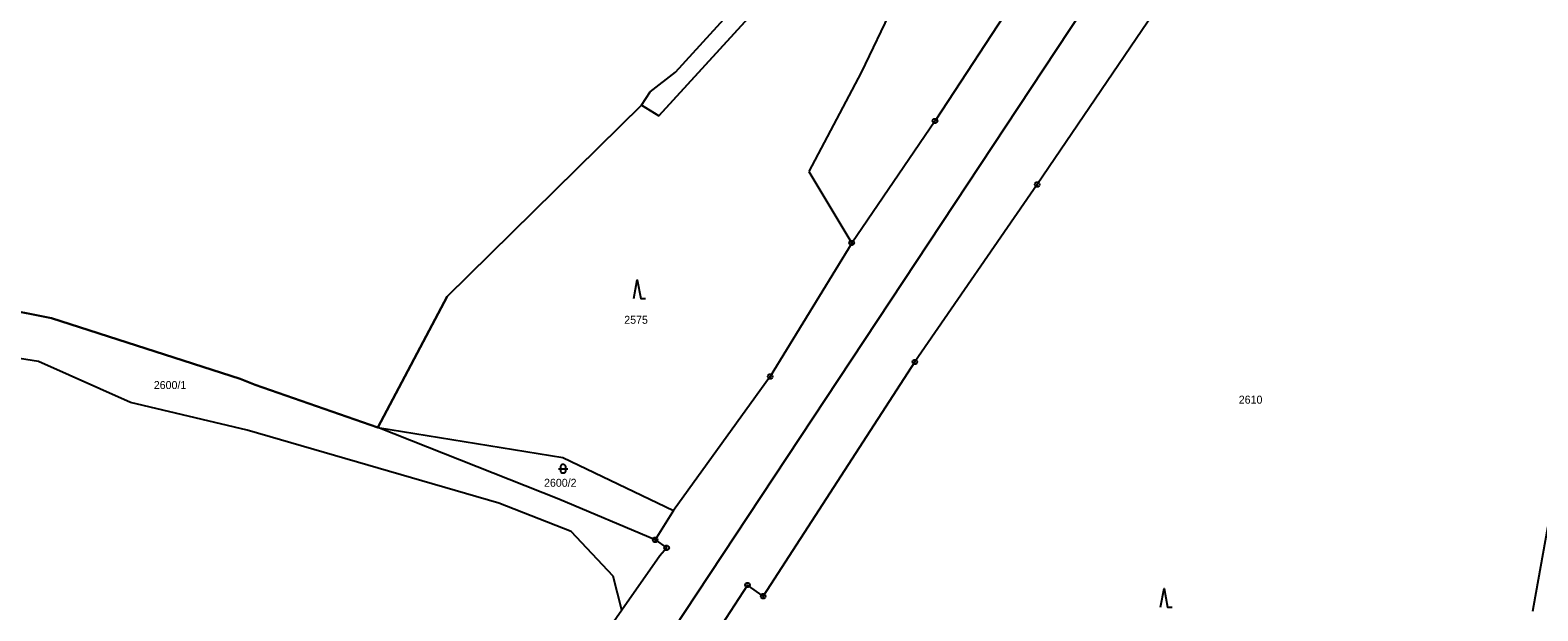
# Model space of a CAD drawing. Extents: x -760611 to -758411, y -1176479 to -1174807.
# Drawn here: x -759798.8 to -759476.2, y -1176113.5 to -1175989.4 of the extents above; entities that cross this region are included whole.
import ezdxf

# ---------------------------------------------------------------- set-up
doc = ezdxf.new("R2010")
doc.units = 0
for name, color, linetype in [('1', 7, 'Continuous'), ('11', 7, 'Continuous'), ('2', 7, 'Continuous'), ('3', 7, 'Continuous'), ('6', 7, 'Continuous'), ('8', 7, 'Continuous')]:
    doc.layers.add(name, color=color, linetype=linetype)

msp = doc.modelspace()

# ---------------------------------------------------------------- linework, layer by layer
at = {"layer": '1'}
for p, q in [((-759578.18, -1175967.56), (-759605.19, -1176008.78)), ((-759660.74, -1175998.38), (-759641.25, -1175976.94)), ((-759555.51, -1175981.46), (-759583.34, -1176022.38)), ((-759614.19, -1175984.28), (-759620.96, -1175998.45)), ((-759645.08, -1175986.7), (-759664.29, -1176007.68)), ((-759666.09, -1176002.55), (-759660.74, -1175998.38)), ((-759620.96, -1175998.45), (-759632.18, -1176019.57)), ((-759667.97, -1176005.44), (-759709.52, -1176046.31)), ((-759667.97, -1176005.44), (-759666.09, -1176002.55)), ((-759664.29, -1176007.68), (-759667.97, -1176005.44)), ((-759605.19, -1176008.78), (-759623.01, -1176034.88)), ((-759632.18, -1176019.57), (-759623.01, -1176034.88)), ((-759583.34, -1176022.38), (-759609.49, -1176060.32)), ((-759623.01, -1176034.88), (-759640.44, -1176063.43)), ((-759794.18, -1176050.97), (-759814.38, -1176046.99)), ((-759709.52, -1176046.31), (-759724.36, -1176074.33)), ((-759753.8, -1176063.91), (-759794.18, -1176050.97)), ((-759796.99, -1176060.22), (-759818.71, -1176056.82)), ((-759777.26, -1176068.95), (-759796.99, -1176060.22)), ((-759609.49, -1176060.32), (-759641.95, -1176110.4)), ((-759640.44, -1176063.43), (-759661.14, -1176092.07)), ((-759750.6, -1176065.19), (-759753.8, -1176063.91)), ((-759724.36, -1176074.33), (-759750.6, -1176065.19)), ((-759752.37, -1176074.92), (-759777.26, -1176068.95)), ((-759469.14, -1176067.99), (-759477.14, -1176112.43)), ((-759698.51, -1176090.48), (-759752.37, -1176074.92)), ((-759685.68, -1176089.67), (-759724.36, -1176074.33)), ((-759724.36, -1176074.33), (-759684.84, -1176080.74)), ((-759684.84, -1176080.74), (-759661.14, -1176092.07)), ((-759683.03, -1176096.6), (-759698.51, -1176090.48)), ((-759665.06, -1176098.36), (-759685.68, -1176089.67)), ((-759661.14, -1176092.07), (-759665.06, -1176098.36)), ((-759674.01, -1176106.12), (-759683.03, -1176096.6)), ((-759665.06, -1176098.36), (-759662.59, -1176100.07)), ((-759664.06, -1176101.76), (-759672.16, -1176113.37)), ((-759662.59, -1176100.07), (-759664.06, -1176101.76)), ((-759672.16, -1176113.37), (-759674.01, -1176106.12)), ((-759645.3, -1176108.02), (-759655.18, -1176123.17)), ((-759641.95, -1176110.4), (-759645.3, -1176108.02)), ((-759672.16, -1176113.37), (-759732.47, -1176199.81)), ((-759477.14, -1176112.43), (-759477.37, -1176113.69))]:
    msp.add_line(p, q, dxfattribs=at)
at = {"layer": '11'}
msp.add_lwpolyline([(-759814.38, -1176046.99), (-759794.18, -1176050.97), (-759753.8, -1176063.91), (-759750.6, -1176065.19), (-759724.36, -1176074.33), (-759709.52, -1176046.31), (-759667.97, -1176005.44), (-759664.29, -1176007.68), (-759645.08, -1175986.7), (-759610.38, -1175933.87), (-759613.04, -1175914.7), (-759616.82, -1175900.35), (-759617.87, -1175896.37), (-759624.08, -1175883.65), (-759626.24, -1175882.35), (-759636, -1175876.49), (-759638.48, -1175875), (-759636.48, -1175873.71), (-759627.47, -1175867.91), (-759502.75, -1175783.52), (-759461.61, -1175775.54)], dxfattribs=at)
at = {"layer": '3'}
for points in [[(-759669.65, -1176046.75), (-759668.9, -1176042.75), (-759668.15, -1176046.75), (-759667.15, -1176046.75)], [(-759685.77, -1176083.14), (-759684.5, -1176083.14), (-759683.77, -1176083.14)], [(-759556.94, -1176112.78), (-759556.19, -1176108.78), (-759555.44, -1176112.78), (-759554.44, -1176112.78)]]:
    msp.add_lwpolyline(points, dxfattribs=at)
msp.add_lwpolyline([(-759685.27, -1176082.64), (-759685.17, -1176082.35), (-759684.92, -1176082.17), (-759684.61, -1176082.17), (-759684.36, -1176082.35), (-759684.26, -1176082.64), (-759684.26, -1176083.64), (-759684.36, -1176083.93), (-759684.61, -1176084.11), (-759684.92, -1176084.11), (-759685.17, -1176083.93), (-759685.27, -1176083.64)], close=True, dxfattribs=at)
at = {"layer": '6'}
for p, q in [((-759573.8, -1175985.33), (-759600.99, -1176026.52)), ((-759600.99, -1176026.52), (-759656.22, -1176109.98)), ((-759656.22, -1176109.98), (-759683.74, -1176151.52))]:
    msp.add_line(p, q, dxfattribs=at)
at = {"layer": '8'}
for p, q in [((-759605.31, -1176008.78), (-759605.07, -1176008.78)), ((-759583.46, -1176022.38), (-759583.22, -1176022.38)), ((-759623.13, -1176034.88), (-759622.89, -1176034.88)), ((-759609.61, -1176060.32), (-759609.37, -1176060.32)), ((-759640.56, -1176063.43), (-759640.32, -1176063.43)), ((-759665.18, -1176098.36), (-759664.94, -1176098.36)), ((-759662.71, -1176100.07), (-759662.47, -1176100.07)), ((-759645.42, -1176108.02), (-759645.18, -1176108.02)), ((-759642.07, -1176110.4), (-759641.83, -1176110.4))]:
    msp.add_line(p, q, dxfattribs=at)
for points in [[(-759605.04, -1176008.3), (-759604.79, -1176008.48), (-759604.69, -1176008.77), (-759604.79, -1176009.06), (-759605.04, -1176009.24), (-759605.35, -1176009.24), (-759605.6, -1176009.06), (-759605.7, -1176008.77), (-759605.6, -1176008.48), (-759605.35, -1176008.3)], [(-759583.19, -1176021.9), (-759582.94, -1176022.08), (-759582.84, -1176022.37), (-759582.94, -1176022.66), (-759583.19, -1176022.84), (-759583.5, -1176022.84), (-759583.75, -1176022.66), (-759583.85, -1176022.37), (-759583.75, -1176022.08), (-759583.5, -1176021.9)], [(-759622.86, -1176034.4), (-759622.61, -1176034.58), (-759622.51, -1176034.87), (-759622.61, -1176035.16), (-759622.86, -1176035.34), (-759623.17, -1176035.34), (-759623.42, -1176035.16), (-759623.52, -1176034.87), (-759623.42, -1176034.58), (-759623.17, -1176034.4)], [(-759609.34, -1176059.84), (-759609.09, -1176060.02), (-759608.99, -1176060.31), (-759609.09, -1176060.6), (-759609.34, -1176060.78), (-759609.65, -1176060.78), (-759609.9, -1176060.6), (-759610, -1176060.31), (-759609.9, -1176060.02), (-759609.65, -1176059.84)], [(-759640.29, -1176062.95), (-759640.04, -1176063.13), (-759639.94, -1176063.42), (-759640.04, -1176063.71), (-759640.29, -1176063.89), (-759640.6, -1176063.89), (-759640.85, -1176063.71), (-759640.95, -1176063.42), (-759640.85, -1176063.13), (-759640.6, -1176062.95)], [(-759664.91, -1176097.88), (-759664.66, -1176098.06), (-759664.56, -1176098.35), (-759664.66, -1176098.64), (-759664.91, -1176098.82), (-759665.22, -1176098.82), (-759665.47, -1176098.64), (-759665.57, -1176098.35), (-759665.47, -1176098.06), (-759665.22, -1176097.88)], [(-759662.44, -1176099.59), (-759662.19, -1176099.77), (-759662.09, -1176100.06), (-759662.19, -1176100.35), (-759662.44, -1176100.53), (-759662.75, -1176100.53), (-759663, -1176100.35), (-759663.1, -1176100.06), (-759663, -1176099.77), (-759662.75, -1176099.59)], [(-759645.15, -1176107.54), (-759644.9, -1176107.72), (-759644.8, -1176108.01), (-759644.9, -1176108.3), (-759645.15, -1176108.48), (-759645.46, -1176108.48), (-759645.71, -1176108.3), (-759645.81, -1176108.01), (-759645.71, -1176107.72), (-759645.46, -1176107.54)], [(-759641.8, -1176109.92), (-759641.55, -1176110.1), (-759641.45, -1176110.39), (-759641.55, -1176110.68), (-759641.8, -1176110.86), (-759642.11, -1176110.86), (-759642.36, -1176110.68), (-759642.46, -1176110.39), (-759642.36, -1176110.1), (-759642.11, -1176109.92)]]:
    msp.add_lwpolyline(points, close=True, dxfattribs=at)

# ---------------------------------------------------------------- texts
at = {"layer": '2'}
for s, p in [('2575', (-759671.67, -1176052.15)), ('2600/1', (-759772.31, -1176066.1)), ('2610', (-759540.21, -1176069.23)), ('2600/2', (-759688.83, -1176087))]:
    msp.add_text(s, height=1.7, dxfattribs=at).set_placement(p)

doc.saveas('drawing.dxf')
